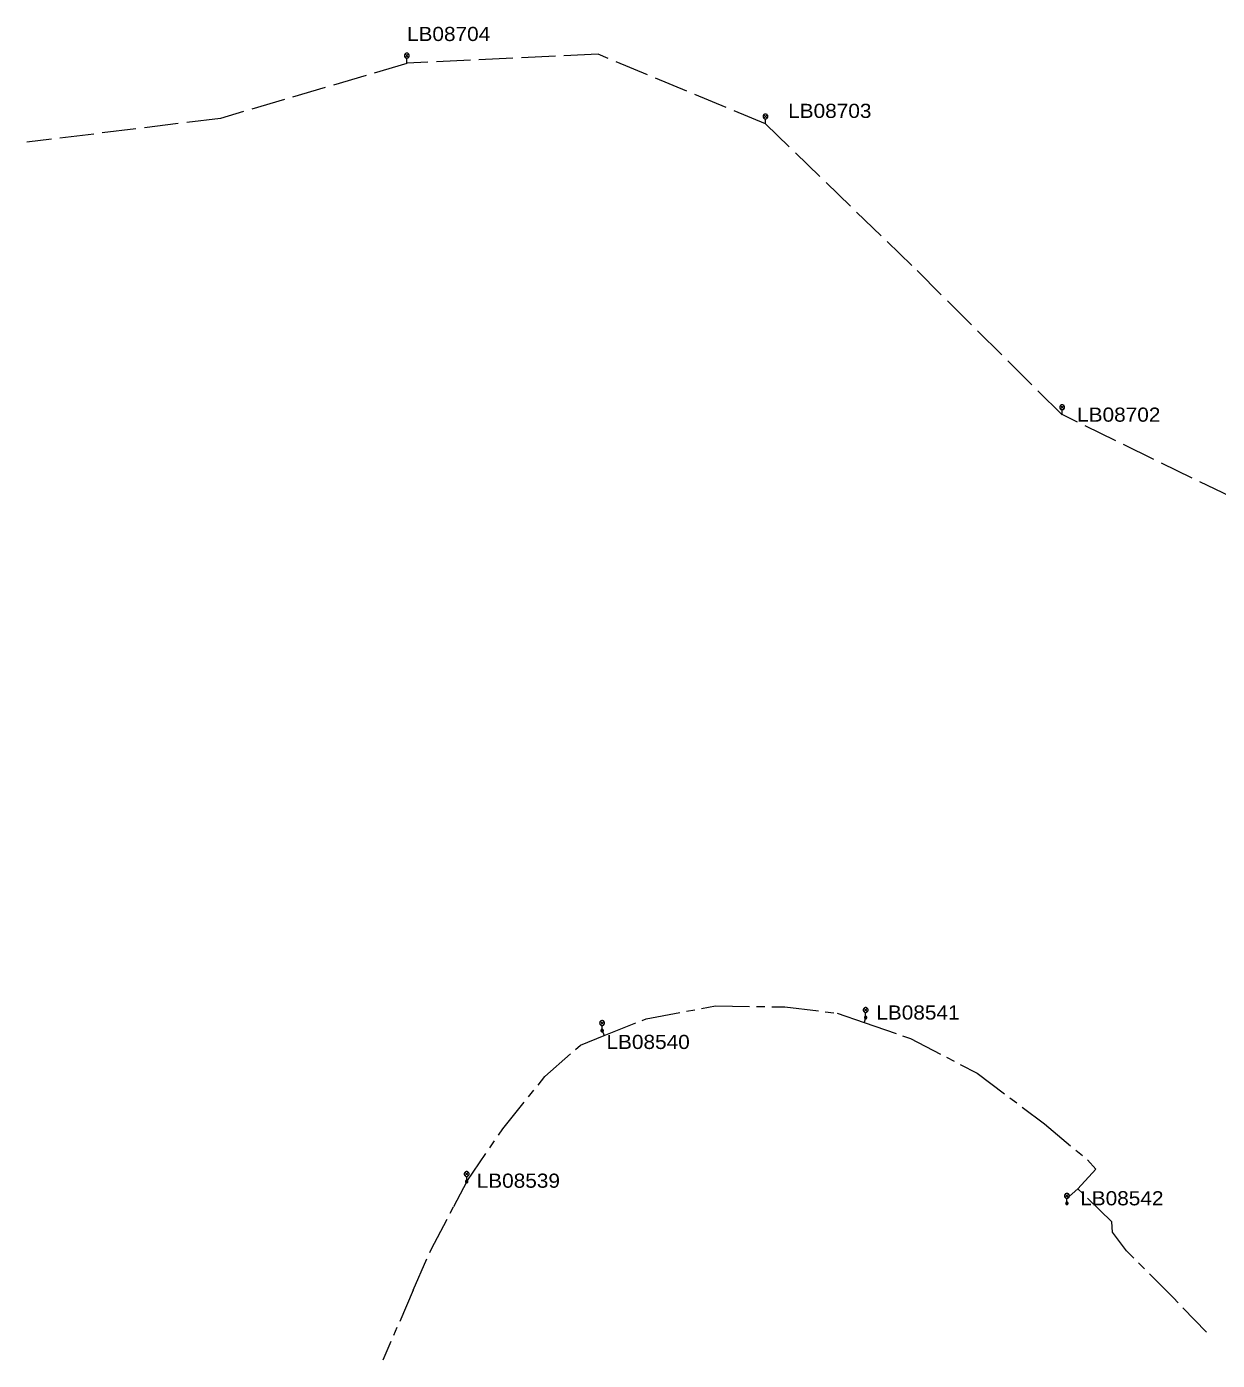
# Model space of a CAD drawing. Extents: x -686371 to -686009, y -974088 to -973838.
# Drawn here: x -686370.6 to -686188.2, y -974080 to -973875.7 of the extents above; entities that cross this region are included whole.
import ezdxf

# ---------------------------------------------------------------- set-up
doc = ezdxf.new("R2010")
doc.units = 0
doc.header["$LTSCALE"] = 0.87
doc.linetypes.add('LONG_DASH_SHORT_DASH', pattern=[9.9, 6, -1.2, 1.5, -1.2])
doc.linetypes.add('LONG_DASHED', pattern=[7.5, 6, -1.5])
doc.layers.add('1', color=7, linetype='Continuous', lineweight=13)

msp = doc.modelspace()

# ---------------------------------------------------------------- linework, layer by layer
at = {"layer": '1'}
for p, q in [((-686312.645, -973879.825), (-686312.115, -973880.355)), ((-686312.645, -973880.355), (-686312.115, -973879.825)), ((-686312.38, -973881.24), (-686312.38, -973880.465)), ((-686257.695, -973889.145), (-686257.165, -973889.675)), ((-686257.695, -973889.675), (-686257.165, -973889.145)), ((-686257.43, -973890.56), (-686257.43, -973889.785)), ((-686212.235, -973933.695), (-686211.705, -973934.225)), ((-686212.235, -973934.225), (-686211.705, -973933.695)), ((-686211.97, -973935.11), (-686211.97, -973934.335)), ((-686242.345, -974026.045), (-686241.815, -974026.575)), ((-686242.345, -974026.575), (-686241.815, -974026.045)), ((-686242.08, -974027.46), (-686242.08, -974026.685)), ((-686282.725, -974028.045), (-686282.195, -974028.575)), ((-686282.725, -974028.575), (-686282.195, -974028.045)), ((-686282.46, -974029.46), (-686282.46, -974028.685)), ((-686303.475, -974051.175), (-686302.945, -974051.705)), ((-686303.475, -974051.705), (-686302.945, -974051.175)), ((-686303.21, -974052.59), (-686303.21, -974051.815)), ((-686211.505, -974054.515), (-686210.975, -974055.045)), ((-686211.505, -974055.045), (-686210.975, -974054.515)), ((-686211.24, -974055.93), (-686211.24, -974055.155))]:
    msp.add_line(p, q, dxfattribs=at)
at = {"layer": '1', "linetype": 'LONG_DASHED'}
msp.add_line((-686186.16, -973947.66), (-686211.97, -973935.089), dxfattribs=at)
at = {"layer": '1', "linetype": 'LONG_DASH_SHORT_DASH'}
for p, q in [((-686275.7, -974027.65), (-686265.09, -974025.68)), ((-686265.09, -974025.68), (-686254.48, -974025.84)), ((-686254.48, -974025.84), (-686246.44, -974026.78)), ((-686246.44, -974026.78), (-686242.33, -974028.2)), ((-686242.08, -974027.46), (-686242.33, -974028.2)), ((-686242.33, -974028.2), (-686235.23, -974030.65)), ((-686285.78, -974031.68), (-686282.15, -974030.23)), ((-686235.23, -974030.65), (-686224.98, -974036)), ((-686208.1, -974049.25), (-686206.82, -974050.67)), ((-686206.82, -974050.67), (-686209.54, -974053.69)), ((-686303.21, -974052.59), (-686305.21, -974056.44)), ((-686209.54, -974053.69), (-686211.31, -974055.24)), ((-686211.31, -974055.24), (-686211.24, -974055.93)), ((-686204.34, -974058.78), (-686209.54, -974053.69)), ((-686204.23, -974060.34), (-686204.34, -974058.78)), ((-686311.4, -974069.22), (-686316.07, -974079.98))]:
    msp.add_line(p, q, dxfattribs=at)
at = {"layer": '1'}
for points in [[(-686312.005, -973880.09), (-686312.011, -973880.025), (-686312.028, -973879.962), (-686312.055, -973879.903), (-686312.093, -973879.849), (-686312.139, -973879.803), (-686312.192, -973879.765), (-686312.252, -973879.738), (-686312.315, -973879.721), (-686312.38, -973879.715), (-686312.445, -973879.721), (-686312.508, -973879.738), (-686312.568, -973879.765), (-686312.621, -973879.803), (-686312.667, -973879.849), (-686312.705, -973879.903), (-686312.732, -973879.962), (-686312.749, -973880.025), (-686312.755, -973880.09), (-686312.749, -973880.155), (-686312.732, -973880.218), (-686312.705, -973880.278), (-686312.667, -973880.331), (-686312.621, -973880.377), (-686312.568, -973880.415), (-686312.508, -973880.442), (-686312.445, -973880.459), (-686312.38, -973880.465), (-686312.315, -973880.459), (-686312.252, -973880.442), (-686312.192, -973880.415), (-686312.139, -973880.377), (-686312.093, -973880.331), (-686312.055, -973880.278), (-686312.028, -973880.218), (-686312.011, -973880.155)], [(-686257.055, -973889.41), (-686257.061, -973889.345), (-686257.078, -973889.282), (-686257.105, -973889.222), (-686257.143, -973889.169), (-686257.189, -973889.123), (-686257.242, -973889.085), (-686257.302, -973889.058), (-686257.365, -973889.041), (-686257.43, -973889.035), (-686257.495, -973889.041), (-686257.558, -973889.058), (-686257.618, -973889.085), (-686257.671, -973889.123), (-686257.717, -973889.169), (-686257.755, -973889.222), (-686257.782, -973889.282), (-686257.799, -973889.345), (-686257.805, -973889.41), (-686257.799, -973889.475), (-686257.782, -973889.538), (-686257.755, -973889.598), (-686257.717, -973889.651), (-686257.671, -973889.697), (-686257.618, -973889.735), (-686257.558, -973889.762), (-686257.495, -973889.779), (-686257.43, -973889.785), (-686257.365, -973889.779), (-686257.302, -973889.762), (-686257.242, -973889.735), (-686257.189, -973889.697), (-686257.143, -973889.651), (-686257.105, -973889.598), (-686257.078, -973889.538), (-686257.061, -973889.475)], [(-686211.595, -973933.96), (-686211.601, -973933.895), (-686211.618, -973933.832), (-686211.645, -973933.772), (-686211.683, -973933.719), (-686211.729, -973933.673), (-686211.782, -973933.635), (-686211.842, -973933.608), (-686211.905, -973933.591), (-686211.97, -973933.585), (-686212.035, -973933.591), (-686212.098, -973933.608), (-686212.158, -973933.635), (-686212.211, -973933.673), (-686212.257, -973933.719), (-686212.295, -973933.772), (-686212.322, -973933.832), (-686212.339, -973933.895), (-686212.345, -973933.96), (-686212.339, -973934.025), (-686212.322, -973934.088), (-686212.295, -973934.148), (-686212.257, -973934.201), (-686212.211, -973934.247), (-686212.158, -973934.285), (-686212.098, -973934.312), (-686212.035, -973934.329), (-686211.97, -973934.335), (-686211.905, -973934.329), (-686211.842, -973934.312), (-686211.782, -973934.285), (-686211.729, -973934.247), (-686211.683, -973934.201), (-686211.645, -973934.148), (-686211.618, -973934.088), (-686211.601, -973934.025)], [(-686241.705, -974026.31), (-686241.711, -974026.245), (-686241.728, -974026.182), (-686241.755, -974026.122), (-686241.793, -974026.069), (-686241.839, -974026.023), (-686241.892, -974025.985), (-686241.952, -974025.958), (-686242.015, -974025.941), (-686242.08, -974025.935), (-686242.145, -974025.941), (-686242.208, -974025.958), (-686242.268, -974025.985), (-686242.321, -974026.023), (-686242.367, -974026.069), (-686242.405, -974026.122), (-686242.432, -974026.182), (-686242.449, -974026.245), (-686242.455, -974026.31), (-686242.449, -974026.375), (-686242.432, -974026.438), (-686242.405, -974026.497), (-686242.367, -974026.551), (-686242.321, -974026.597), (-686242.268, -974026.635), (-686242.208, -974026.662), (-686242.145, -974026.679), (-686242.08, -974026.685), (-686242.015, -974026.679), (-686241.952, -974026.662), (-686241.892, -974026.635), (-686241.839, -974026.597), (-686241.793, -974026.551), (-686241.755, -974026.497), (-686241.728, -974026.438), (-686241.711, -974026.375)], [(-686282.085, -974028.31), (-686282.091, -974028.245), (-686282.108, -974028.182), (-686282.135, -974028.122), (-686282.173, -974028.069), (-686282.219, -974028.023), (-686282.272, -974027.985), (-686282.332, -974027.958), (-686282.395, -974027.941), (-686282.46, -974027.935), (-686282.525, -974027.941), (-686282.588, -974027.958), (-686282.648, -974027.985), (-686282.701, -974028.023), (-686282.747, -974028.069), (-686282.785, -974028.122), (-686282.812, -974028.182), (-686282.829, -974028.245), (-686282.835, -974028.31), (-686282.829, -974028.375), (-686282.812, -974028.438), (-686282.785, -974028.497), (-686282.747, -974028.551), (-686282.701, -974028.597), (-686282.648, -974028.635), (-686282.588, -974028.662), (-686282.525, -974028.679), (-686282.46, -974028.685), (-686282.395, -974028.679), (-686282.332, -974028.662), (-686282.272, -974028.635), (-686282.219, -974028.597), (-686282.173, -974028.551), (-686282.135, -974028.497), (-686282.108, -974028.438), (-686282.091, -974028.375)], [(-686241.89, -974027.46), (-686241.893, -974027.427), (-686241.901, -974027.395), (-686241.915, -974027.365), (-686241.934, -974027.338), (-686241.958, -974027.314), (-686241.985, -974027.295), (-686242.015, -974027.281), (-686242.047, -974027.273), (-686242.08, -974027.27), (-686242.113, -974027.273), (-686242.145, -974027.281), (-686242.175, -974027.295), (-686242.202, -974027.314), (-686242.226, -974027.338), (-686242.245, -974027.365), (-686242.259, -974027.395), (-686242.267, -974027.427), (-686242.27, -974027.46), (-686242.267, -974027.493), (-686242.259, -974027.525), (-686242.245, -974027.555), (-686242.226, -974027.582), (-686242.202, -974027.606), (-686242.175, -974027.625), (-686242.145, -974027.639), (-686242.113, -974027.647), (-686242.08, -974027.65), (-686242.047, -974027.647), (-686242.015, -974027.639), (-686241.985, -974027.625), (-686241.958, -974027.606), (-686241.934, -974027.582), (-686241.915, -974027.555), (-686241.901, -974027.525), (-686241.893, -974027.493)], [(-686242.03, -974027.46), (-686242.031, -974027.451), (-686242.033, -974027.443), (-686242.037, -974027.435), (-686242.042, -974027.428), (-686242.048, -974027.422), (-686242.055, -974027.417), (-686242.063, -974027.413), (-686242.071, -974027.411), (-686242.08, -974027.41), (-686242.089, -974027.411), (-686242.097, -974027.413), (-686242.105, -974027.417), (-686242.112, -974027.422), (-686242.118, -974027.428), (-686242.123, -974027.435), (-686242.127, -974027.443), (-686242.129, -974027.451), (-686242.13, -974027.46), (-686242.129, -974027.469), (-686242.127, -974027.477), (-686242.123, -974027.485), (-686242.118, -974027.492), (-686242.112, -974027.498), (-686242.105, -974027.503), (-686242.097, -974027.507), (-686242.089, -974027.509), (-686242.08, -974027.51), (-686242.071, -974027.509), (-686242.063, -974027.507), (-686242.055, -974027.503), (-686242.048, -974027.498), (-686242.042, -974027.492), (-686242.037, -974027.485), (-686242.033, -974027.477), (-686242.031, -974027.469)], [(-686282.27, -974029.46), (-686282.273, -974029.427), (-686282.281, -974029.395), (-686282.295, -974029.365), (-686282.314, -974029.338), (-686282.338, -974029.314), (-686282.365, -974029.295), (-686282.395, -974029.281), (-686282.427, -974029.273), (-686282.46, -974029.27), (-686282.493, -974029.273), (-686282.525, -974029.281), (-686282.555, -974029.295), (-686282.582, -974029.314), (-686282.606, -974029.338), (-686282.625, -974029.365), (-686282.639, -974029.395), (-686282.647, -974029.427), (-686282.65, -974029.46), (-686282.647, -974029.493), (-686282.639, -974029.525), (-686282.625, -974029.555), (-686282.606, -974029.582), (-686282.582, -974029.606), (-686282.555, -974029.625), (-686282.525, -974029.639), (-686282.493, -974029.647), (-686282.46, -974029.65), (-686282.427, -974029.647), (-686282.395, -974029.639), (-686282.365, -974029.625), (-686282.338, -974029.606), (-686282.314, -974029.582), (-686282.295, -974029.555), (-686282.281, -974029.525), (-686282.273, -974029.493)], [(-686282.41, -974029.46), (-686282.411, -974029.451), (-686282.413, -974029.443), (-686282.417, -974029.435), (-686282.422, -974029.428), (-686282.428, -974029.422), (-686282.435, -974029.417), (-686282.443, -974029.413), (-686282.451, -974029.411), (-686282.46, -974029.41), (-686282.469, -974029.411), (-686282.477, -974029.413), (-686282.485, -974029.417), (-686282.492, -974029.422), (-686282.498, -974029.428), (-686282.503, -974029.435), (-686282.507, -974029.443), (-686282.509, -974029.451), (-686282.51, -974029.46), (-686282.509, -974029.469), (-686282.507, -974029.477), (-686282.503, -974029.485), (-686282.498, -974029.492), (-686282.492, -974029.498), (-686282.485, -974029.503), (-686282.477, -974029.507), (-686282.469, -974029.509), (-686282.46, -974029.51), (-686282.451, -974029.509), (-686282.443, -974029.507), (-686282.435, -974029.503), (-686282.428, -974029.498), (-686282.422, -974029.492), (-686282.417, -974029.485), (-686282.413, -974029.477), (-686282.411, -974029.469)], [(-686302.835, -974051.44), (-686302.841, -974051.375), (-686302.858, -974051.312), (-686302.885, -974051.253), (-686302.923, -974051.199), (-686302.969, -974051.153), (-686303.022, -974051.115), (-686303.082, -974051.088), (-686303.145, -974051.071), (-686303.21, -974051.065), (-686303.275, -974051.071), (-686303.338, -974051.088), (-686303.398, -974051.115), (-686303.451, -974051.153), (-686303.497, -974051.199), (-686303.535, -974051.253), (-686303.562, -974051.312), (-686303.579, -974051.375), (-686303.585, -974051.44), (-686303.579, -974051.505), (-686303.562, -974051.568), (-686303.535, -974051.628), (-686303.497, -974051.681), (-686303.451, -974051.727), (-686303.398, -974051.765), (-686303.338, -974051.792), (-686303.275, -974051.809), (-686303.21, -974051.815), (-686303.145, -974051.809), (-686303.082, -974051.792), (-686303.022, -974051.765), (-686302.969, -974051.727), (-686302.923, -974051.681), (-686302.885, -974051.628), (-686302.858, -974051.568), (-686302.841, -974051.505)], [(-686303.02, -974052.59), (-686303.023, -974052.557), (-686303.031, -974052.525), (-686303.045, -974052.495), (-686303.064, -974052.468), (-686303.088, -974052.444), (-686303.115, -974052.425), (-686303.145, -974052.411), (-686303.177, -974052.403), (-686303.21, -974052.4), (-686303.243, -974052.403), (-686303.275, -974052.411), (-686303.305, -974052.425), (-686303.332, -974052.444), (-686303.356, -974052.468), (-686303.375, -974052.495), (-686303.389, -974052.525), (-686303.397, -974052.557), (-686303.4, -974052.59), (-686303.397, -974052.623), (-686303.389, -974052.655), (-686303.375, -974052.685), (-686303.356, -974052.712), (-686303.332, -974052.736), (-686303.305, -974052.755), (-686303.275, -974052.769), (-686303.243, -974052.777), (-686303.21, -974052.78), (-686303.177, -974052.777), (-686303.145, -974052.769), (-686303.115, -974052.755), (-686303.088, -974052.736), (-686303.064, -974052.712), (-686303.045, -974052.685), (-686303.031, -974052.655), (-686303.023, -974052.623)], [(-686303.16, -974052.59), (-686303.161, -974052.581), (-686303.163, -974052.573), (-686303.167, -974052.565), (-686303.172, -974052.558), (-686303.178, -974052.552), (-686303.185, -974052.547), (-686303.193, -974052.543), (-686303.201, -974052.541), (-686303.21, -974052.54), (-686303.219, -974052.541), (-686303.227, -974052.543), (-686303.235, -974052.547), (-686303.242, -974052.552), (-686303.248, -974052.558), (-686303.253, -974052.565), (-686303.257, -974052.573), (-686303.259, -974052.581), (-686303.26, -974052.59), (-686303.259, -974052.599), (-686303.257, -974052.607), (-686303.253, -974052.615), (-686303.248, -974052.622), (-686303.242, -974052.628), (-686303.235, -974052.633), (-686303.227, -974052.637), (-686303.219, -974052.639), (-686303.21, -974052.64), (-686303.201, -974052.639), (-686303.193, -974052.637), (-686303.185, -974052.633), (-686303.178, -974052.628), (-686303.172, -974052.622), (-686303.167, -974052.615), (-686303.163, -974052.607), (-686303.161, -974052.599)], [(-686210.865, -974054.78), (-686210.871, -974054.715), (-686210.888, -974054.652), (-686210.915, -974054.592), (-686210.953, -974054.539), (-686210.999, -974054.493), (-686211.052, -974054.455), (-686211.112, -974054.428), (-686211.175, -974054.411), (-686211.24, -974054.405), (-686211.305, -974054.411), (-686211.368, -974054.428), (-686211.428, -974054.455), (-686211.481, -974054.493), (-686211.527, -974054.539), (-686211.565, -974054.592), (-686211.592, -974054.652), (-686211.609, -974054.715), (-686211.615, -974054.78), (-686211.609, -974054.845), (-686211.592, -974054.908), (-686211.565, -974054.968), (-686211.527, -974055.021), (-686211.481, -974055.067), (-686211.428, -974055.105), (-686211.368, -974055.132), (-686211.305, -974055.149), (-686211.24, -974055.155), (-686211.175, -974055.149), (-686211.112, -974055.132), (-686211.052, -974055.105), (-686210.999, -974055.067), (-686210.953, -974055.021), (-686210.915, -974054.968), (-686210.888, -974054.908), (-686210.871, -974054.845)], [(-686211.05, -974055.93), (-686211.053, -974055.897), (-686211.061, -974055.865), (-686211.075, -974055.835), (-686211.094, -974055.808), (-686211.118, -974055.784), (-686211.145, -974055.765), (-686211.175, -974055.751), (-686211.207, -974055.743), (-686211.24, -974055.74), (-686211.273, -974055.743), (-686211.305, -974055.751), (-686211.335, -974055.765), (-686211.362, -974055.784), (-686211.386, -974055.808), (-686211.405, -974055.835), (-686211.419, -974055.865), (-686211.427, -974055.897), (-686211.43, -974055.93), (-686211.427, -974055.963), (-686211.419, -974055.995), (-686211.405, -974056.025), (-686211.386, -974056.052), (-686211.362, -974056.076), (-686211.335, -974056.095), (-686211.305, -974056.109), (-686211.273, -974056.117), (-686211.24, -974056.12), (-686211.207, -974056.117), (-686211.175, -974056.109), (-686211.145, -974056.095), (-686211.118, -974056.076), (-686211.094, -974056.052), (-686211.075, -974056.025), (-686211.061, -974055.995), (-686211.053, -974055.963)], [(-686211.19, -974055.93), (-686211.191, -974055.921), (-686211.193, -974055.913), (-686211.197, -974055.905), (-686211.202, -974055.898), (-686211.208, -974055.892), (-686211.215, -974055.887), (-686211.223, -974055.883), (-686211.231, -974055.881), (-686211.24, -974055.88), (-686211.249, -974055.881), (-686211.257, -974055.883), (-686211.265, -974055.887), (-686211.272, -974055.892), (-686211.278, -974055.898), (-686211.283, -974055.905), (-686211.287, -974055.913), (-686211.289, -974055.921), (-686211.29, -974055.93), (-686211.289, -974055.939), (-686211.287, -974055.947), (-686211.283, -974055.955), (-686211.278, -974055.962), (-686211.272, -974055.968), (-686211.265, -974055.973), (-686211.257, -974055.977), (-686211.249, -974055.979), (-686211.24, -974055.98), (-686211.231, -974055.979), (-686211.223, -974055.977), (-686211.215, -974055.973), (-686211.208, -974055.968), (-686211.202, -974055.962), (-686211.197, -974055.955), (-686211.193, -974055.947), (-686211.191, -974055.939)]]:
    msp.add_lwpolyline(points, close=True, dxfattribs=at)
at = {"layer": '1', "linetype": 'LONG_DASHED'}
for points in [[(-686312.369, -973881.308), (-686340.934, -973889.704), (-686370.638, -973893.369)], [(-686257.428, -973890.564), (-686283.09, -973879.89), (-686312.38, -973881.23)], [(-686211.97, -973935.11), (-686235.01, -973912.22), (-686257.43, -973890.56)]]:
    msp.add_lwpolyline(points, dxfattribs=at)
at = {"layer": '1', "linetype": 'LONG_DASH_SHORT_DASH'}
for points in [[(-686282.46, -974029.46), (-686282.15, -974030.23), (-686275.7, -974027.65)], [(-686303.21, -974052.59), (-686297.68, -974044.5), (-686291.22, -974036.5), (-686285.78, -974031.68)], [(-686224.98, -974036), (-686214.68, -974043.76), (-686208.1, -974049.25)], [(-686311.4, -974069.22), (-686308.66, -974062.98), (-686305.21, -974056.44)], [(-686189.84, -974075.68), (-686194.9, -974070.41), (-686202.13, -974063.18), (-686204.23, -974060.34)]]:
    msp.add_lwpolyline(points, dxfattribs=at)

# ---------------------------------------------------------------- texts
at = {"layer": '1', "width": 1.1}
for s, p in [('LB08704', (-686312.365, -973877.854)), ('LB08703', (-686253.951, -973889.637)), ('LB08702', (-686209.672, -973936.177)), ('LB08541', (-686240.447, -974027.775)), ('LB08540', (-686281.79, -974032.283)), ('LB08539', (-686301.68, -974053.542)), ('LB08542', (-686209.201, -974056.235))]:
    msp.add_text(s, height=2.167, dxfattribs=at).set_placement(p)

doc.saveas('drawing.dxf')
